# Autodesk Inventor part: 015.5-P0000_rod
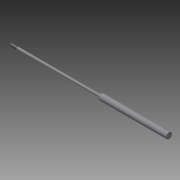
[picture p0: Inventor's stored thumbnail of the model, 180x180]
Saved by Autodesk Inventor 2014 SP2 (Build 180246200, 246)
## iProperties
Created: 2020-01
Part Number: 015.5-P0000_rod
Material: Generic
Catalog Web Link: www.cadenas.de
Description: Standard Air Cylinder_rod-Original Line - Standard Air Cylinders
Vendor: BIMBA
Document SubType Name: Modeling
Designer: psadmin
Manufacturer: BIMBA
Mass: 15.5246 g
Surface Area: 71.9082 cm^2
Volume: 15.5246 cm^3
Density: 1 g/cm^3
Appearance: PSOLRGB-181-181-181
Category: PARTsolutions
Company: BIMBA
Title: 015.5-P0000_rod
Author: Cadenas PARTsolutions
Comments: Original Line - Standard Air Cylinders
PSOL_IDENT_0: {$CADENAS_DATA\23d-libs\bimba\bimba_brand\bimba_imperial\bimba_full_line\original_line_cylinders\sta
PSOL_IDENT_1: ndard_air_cylinders\rod.prj},331 {VTYP=3D},{NB=015.5-P0000_rod},{LINA=015.5-P0000_rod},{NN=Standard
PSOL_IDENT_2: Air Cylinder_rod},{DATE=23.12.2019 10:36:48},{GEOMDATE=27.08.2019 11:00:52},{VERSION=},{LINEID=30},{
PSOL_IDENT_3: WBVAR=STROKE,ACTING,MNT,DER,NR,BM,CO,M,EE,EEL,K,Q,Y,F,G,T,B,H,SER,SR,NT,W,E,HL,ST,STP,PRC,PB,COLOR1,
PSOL_IDENT_4: FCD,RCD,BCD,ZHJ},{WBNUMERIC=STROKE,EEL,COLOR1,FCD,RCD,BCD,ZHJ}  {NB=015.5-P0000_rod},{LINA=015.5-P00
PSOL_IDENT_5: 00_rod},{KT=DUMMY},{PN=015.5-P000},{DASH=-},{BORE=0.43750000},{BOREPN=01},{STROKE=5.500},{STROKEALG=
PSOL_IDENT_6: [0.001:50/0.001]},{STROKE1=5.500},{ACTING=},{ACTINGALG= '' , 'Single Acting' , 'R' , 'Reverse Single
PSOL_IDENT_7: Acting' , 'D' , 'Double Acting' },{ACTINGPN=},{MNT=P},{MNTALG= '' , 'Front Nose Mounting' , 'P' , '
PSOL_IDENT_8: Rear Pivot Mounting' , 'BF' , 'Front Block Mounting' , 'BR' , 'Rear Block Mounting for Vertical Posi
PSOL_IDENT_9: tioning' , 'BFT' , 'Front Block Trunnion Mounting' , 'BRT' , 'Rear Block Trunnion Mounting' },{TYPE=
PSOL_IDENT_10: },{MNTPN=P},{DER=},{DERALG= '' , 'N/A' },{NR=},{NRALG= '' , 'Standard' , 'NR' , 'Non-rotating - Hexa
PSOL_IDENT_11: gon Rod' },{NRPN=},{BM=},{BMALG= '' , 'N/A' },{BMPN=},{CO=},{COALG= '' , 'N/A' },{M=},{MALG= '', 'Wi
PSOL_IDENT_12: thout Magnet', 'M', 'With Magnet' },{EE=},{EEL=0},{EEMAX=44},{EEALG= '', 'Without Extra Extension', '
PSOL_IDENT_13: EE', 'With Extra Extension' },{EELALG=0},{EEPN=},{EEPN1=0.000},{K=},{KALG= '', 'Standard' , 'K' , 'P
PSOL_IDENT_14: orts Rotated 90deg' },{KPN=},{Q=},{QALG= '' , 'Without Side Ported Rear Head' , 'Q' , 'With Side Por
PSOL_IDENT_15: ted Rear Head' },{QPN=},{Y=},{YALG= '' , 'Without Pivot Bushing' , 'Y' , 'With Pivot Bushing' },{YPN=
PSOL_IDENT_16: },{F=},{FALG= '', 'Standard', 'F', 'Molycoated Body' },{FPN=},{G=},{GPN=},{T=},{TALG= '' , 'Standard'
PSOL_IDENT_17: , 'N' , 'Low Temperature' , 'V' , 'High Temperature' },{NPN=},{VPN=},{B=},{BALG= '', 'Without Bumpe
PSOL_IDENT_18: r' , 'B' , 'With Bumper' },{BPN=},{H=},{HALG= '', 'N/A' },{HPN=},{SER=},{SERALG= '' , 'N/A' },{SR=},
PSOL_IDENT_19: {SRALG= 'C' , 'Carbon Steel Rod' , 'SR' , '303 Stainless Steel Rod' , '' , '303 Stainless Steel Rod1'
PSOL_IDENT_20: },{SRPN=},{SRCON=0},{NT=},{NTPN=},{W=},{WALG= '' , 'N/A' },{WPN=},{E=},{EALG= '' , 'Without Special
PSOL_IDENT_21: Lube and Seals' , 'E' , 'With Special Lube and Seals' },{EPN=},{HL=},{HLALG= '' , 'N/A' },{ST=},{ST
PSOL_IDENT_22: ALG= '' , 'Without Switch Track' , 'T' , 'With Switch Track' },{STP=},{STPALG= '' , 'N/A' },{STPN=},
PSOL_IDENT_23: {PRC=},{PRCALG= '' , 'Without Piston Rod Clevis' , 'D-166-1' , 'With Piston Rod Clevis' },{PRCPN=},{
PSOL_IDENT_24: PB=},{PBALG= '' , 'Without Pivot Bracket' , 'D-167' , 'With Pivot Bracket' },{PBPN=},{TLEN=10.8620},
PSOL_IDENT_25: {TEXT=0.466667},{SPACE=0.266667},{FRAC=12.0900},{RGCON=},{RGDACCON=},{RHCON=P},{RHCONON=1},{RHACCON=
PSOL_IDENT_26: },{FNUTCON=0},{RNUTCON=0},{FNUTPN=},{RNUTPN=},{FNUTTRANS=0.0000},{RNUTTRANS=0.0000},{VHOLECON=2},{A1=
PSOL_IDENT_27: 0.6880},{A1N=0.6880},{A1P=1.1880},{A1B=1.1880},{A4=0.2500},{A4N=0.2500},{A4P=0.1880},{A5=0.0200},{A1
PSOL_IDENT_28: H=1.188},{A1NH=0.5000},{A1PH=1.1880},{A1BH=0.8120},{A1SH=0.0000},{A2H=0.1880},{A2NH=0.1880},{LENGTH=
PSOL_IDENT_29: 1.7500},{LENGTH1=1.7500},{LENGTH2=2.6100},{MUL=10.3400},{MUL11=10.3400},{MUL22=15.8400},{MUL33=10.34
PSOL_IDENT_30: 00},{MUL2=0.9400},{MUL211=0.9400},{MUL222=1.4400},{MUL233=0.9400},{SSS=11.0000},{RGLEN=0.4580},{RHLE
PSOL_IDENT_31: N=0.7700},{SSS1=11.0000},{A13=0.9380},{THDLEN1=0.5000},{THD1=0.1900},{TAB=UNF},{THDLEN=0.5000},{THD=
PSOL_IDENT_32: 0.1900},{OD=0.4465},{RODL=11.6520},{PL=4.9640},{RODDIA=0.1870},{HEX=0.1870},{RODTRANS=0.0000},{G1=0.
PSOL_IDENT_33: 0000},{ON=0},{G5=0.0000},{DERLEN=6.6880},{THOLE=0.0000},{WF=0.0000},{BADD=0.0000},{MADD=0.0000},{NVA
PSOL_IDENT_34: DD=0.000},{JRADD=0.00000},{COLOR=0.71,0.71,0.71,0.00},{GROOVE=1},{HOL=0},{D7=0.1590},{H1=0.0000},{D1=
PSOL_IDENT_35: 0.4840},{D1RH=0.7380},{D1P=0.0000},{D1B=0.7380},{D1N=0.4840},{D1NRH=0.4855},{D1BRH=0.4855},{D1PRH=0.
PSOL_IDENT_36: 7380},{BOZO=1},{HADD=0.000},{COLOR1=0},{DEFL=0.0000},{HEXL=0.0000},{SSADD=0.0000},{WFL=0.0000},{MOVE=
PSOL_IDENT_37: 0.0000},{PRCL2=0.37500},{PRCB=0.12000},{PRCTRANS=0.00000},{FCD=0},{RCD=0},{BCD=0},{ZHJ=0.000}
NN: Standard Air Cylinder_rod
NT: Standard
NB: 015.5-P0000_rod
NBSYN: $PN.$COLOR1._rod
LINA: 015.5-P0000_rod
PN: 015.5-P000
BORE: 0.4375
BOREPN: 01
STROKE: 5.5
ACTING: Single Acting
MNT: Rear Pivot Mounting
DER: N/A
NR: Standard
BM: N/A
CO: N/A
M: Without Magnet
EE: Without Extra Extension
EEL: 0
K: Standard
Q: Without Side Ported Rear Head
Y: Without Pivot Bushing
F: Standard
G: Without Magnalube Lubrication
T: Standard
B: Without Bumper
H: N/A
SER: N/A
SR: 303 Stainless Steel Rod1
W: N/A
E: Without Special Lube and Seals
HL: N/A
ST: Without Switch Track
STP: N/A
PRC: Without Piston Rod Clevis
PB: Without Pivot Bracket
A1N: 0.688
A1P: 1.188
A1B: 1.188
A4N: 0.25
A4P: 0.188
A5: 0.02
A1NH: 0.5
A1PH: 1.188
A1BH: 0.812
A1SH: 0
A2NH: 0.188
A13: 0.938
THDLEN1: 0.5
THD1: 0.19
TAB: UNF
OD: 0.4465
RODDIA: 0.187
HEX: 0.187
G1: 0
G5: 0
THOLE: 0
WF: 0
GROOVE: 1
D7: 0.159
D1P: 0
D1B: 0.738
D1N: 0.484
D1NRH: 0.4855
D1BRH: 0.4855
D1PRH: 0.738
COLOR1: 0
FCD: 0
RCD: 0
BCD: 0
ZHJ: 0
SUPPLIER: BIMBA
ARTICLENO: 015.5-P0000_rod
BOMINFO: 015.5-P0000_rod
CREATOR: CADENAS GmbH
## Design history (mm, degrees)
sketch "Sketch_1"
  geometry: L1 (283.261, 0)-(0, 0); L2 (0, 0)-(0, 2.375); L3 (0, 2.375)-(157.175, 2.375); L4 (157.175, 2.375)-(157.175, 5.62); L5 (157.175, 5.62)-(283.261, 5.62); L6 (283.261, 5.62)-(283.261, 0); L7 (283.261, 0)-(0, 0)
  constraints: 14 end point
revolve "Revolution1" sketch "Sketch_1" stored, may be unused: angle "d0" = 360 deg
sketch "Sketch_3"
  geometry: L1 (0, 0)-(-12.7, 0); L2 (-12.7, 0)-(-12.7, 1.941); L3 (-12.7, 1.941)-(-12.228, 2.413); L4 (-12.228, 2.413)-(0, 2.413); L5 (0, 2.413)-(0, 0); L6 (0, 0)-(-12.7, 0)
  constraints: 12 end point
revolve "Revolution2" sketch "Sketch_3" stored, may be unused: angle "d1" = 360 deg
thread "Thread1" dims "d2" = 12.22756, "d3" = 0
sketch "Sketch_30"
  geometry: L1 (0, 0)-(-0.254, 0); L2 (-0.254, 2.159)-(0, 2.159); L3 (0, 2.159)-(0, 2.667); L4 (0, 2.667)-(-0.254, 2.667); L5 (-0.254, 2.667)-(-0.254, 2.159)
  constraints: 10 end point
revolve "Revolution3" sketch "Sketch_30" stored, may be unused: angle "d4" = 360 deg
node "dia1_XY"
node "dia1_YZ"
node "dia1_ZX"
node "dia1_X"
node "dia1_Y"
node "dia1_Z"
node "dia1_Center"
node "dia12_XY"
node "dia12_YZ"
node "dia12_ZX"
node "dia12_X"
node "dia12_Y"
node "dia12_Z"
node "dia12_Center"
node "dia1r_XY"
node "dia1r_YZ"
node "dia1r_ZX"
node "dia1r_X"
node "dia1r_Y"
node "dia1r_Z"
node "dia1r_Center"
node "dia2_XY"
node "dia2_YZ"
node "dia2_ZX"
node "dia2_X"
node "dia2_Y"
node "dia2_Z"
node "dia2_Center"
node "dia22_XY"
node "dia22_YZ"
node "dia22_ZX"
node "dia22_X"
node "dia22_Y"
node "dia22_Z"
node "dia22_Center"
node "dia2r_XY"
node "dia2r_YZ"
node "dia2r_ZX"
node "dia2r_X"
node "dia2r_Y"
node "dia2r_Z"
node "dia2r_Center"
node "rl1_XY"
node "rl1_YZ"
node "rl1_ZX"
node "rl1_X"
node "rl1_Y"
node "rl1_Z"
node "rl1_Center"
node "rl2_XY"
node "rl2_YZ"
node "rl2_ZX"
node "rl2_X"
node "rl2_Y"
node "rl2_Z"
node "rl2_Center"
node "rod_cp_XY"
node "rod_cp_YZ"
node "rod_cp_ZX"
node "rod_cp_X"
node "rod_cp_Y"
node "rod_cp_Z"
node "rod_cp_Center"
node "thd1_XY"
node "thd1_YZ"
node "thd1_ZX"
node "thd1_X"
node "thd1_Y"
node "thd1_Z"
node "thd1_Center"
node "thd2_XY"
node "thd2_YZ"
node "thd2_ZX"
node "thd2_X"
node "thd2_Y"
node "thd2_Z"
node "thd2_Center"
node "to_rod_clevis_XY"
node "to_rod_clevis_YZ"
node "to_rod_clevis_ZX"
node "to_rod_clevis_X"
node "to_rod_clevis_Y"
node "to_rod_clevis_Z"
node "to_rod_clevis_Center"
body "Solid1"
other parameters: "d5" = 0, "d6" = 0, "d7" = 0, "d8" = 0, "d9" = 0, "d10" = 0
